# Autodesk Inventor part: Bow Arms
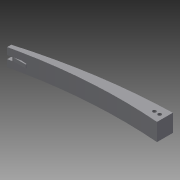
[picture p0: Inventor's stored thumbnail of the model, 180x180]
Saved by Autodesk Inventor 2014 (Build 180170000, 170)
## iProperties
Created: 2013-11
Part Number: Bow Arms
Material: Generic
Document SubType Name: Modeling
Designer: 603839
Density: 1 g/cm^3
Appearance: Default
Author: 603839
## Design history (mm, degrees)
sketch "Sketch1"
  geometry: L1 (-50.8, 15.875)-(50.8, 15.875); L2 (50.8, 15.875)-(50.8, -15.875); L3 (50.8, -15.875)-(-50.8, -15.875); L4 (-50.8, -15.875)-(-50.8, 15.875); L5 (-50.8, 15.875)-(50.8, -15.875); L6 (50.8, 15.875)-(-50.8, -15.875); 1 further point
  constraints: 12 end point, 2 midpoint, 2 parallel, 1 horizontal, 1 perpendicular
  dimensions: "d0" = 101.6 distance of L1.start L1.end; "d1" = 31.75 distance of L1.end L2.end
extrude "Extrusion1" new body sketch "Sketch1" distance "d2" = 19.05; taper "d3" = 0 deg
sketch "Sketch4"
  geometry: L1 (-50.8, -15.875)-(50.8, -15.875) reference; L2 (50.8, -15.875)-(50.8, 15.875) reference; L3 (50.8, 15.875)-(-50.8, 15.875) reference; L4 (-50.8, 15.875)-(-50.8, -15.875) reference; A1 r 402.075 centre (61.562, -386.056) between (50.8, 15.875) and (-50.8, 0); A2 r 337.58 centre (24.07, -332.178) between (50.8, 4.341) and (-50.8, -3.006); 1 further point
  constraints: 4 point on circle, 2 centre point, 2 point on line, 1 midpoint
extrude "Extrusion2" cut sketch "Sketch4" distance "d6" = 19.05; taper "d7" = 0 deg
sketch "Sketch5"
  geometry: L1 (-50.8, 0)-(-50.8, -3.006) reference; L2 (50.8, 4.341)-(50.8, 15.875) reference; A1 r 402.075 centre (61.562, -386.056) between (50.8, 15.875) and (-50.8, 0) reference; A2 r 337.58 centre (24.07, -332.178) between (50.8, 4.341) and (-50.8, -3.006) reference; 1 further point
extrude "Extrusion3" cut sketch "Sketch5" distance "d8" = 6.35; taper "d9" = 0 deg
hole "Hole1" diameter "d12" = 2.54; stored, may be unused: countersink angle "d16" = 82 deg, drill point angle "d18" = 118 deg; dims "d10" = 3.81, "d11" = 25.4, "d13" = 19.05, "d14" = 9.525, "d15" = 6.35, "d17" = 25.4
hole "Hole2" diameter "d21" = 2.54; stored, may be unused: countersink angle "d25" = 82 deg, drill point angle "d27" = 118 deg; dims "d19" = 7.62, "d20" = 25.4, "d22" = 19.05, "d23" = 9.525, "d24" = 6.35, "d26" = 25.4
sketch "Sketch6"
  geometry: L1 (3.006, 0)-(3.006, 5.08); L2 (3.006, 12.7)-(3.006, 7.62); L3 (3.006, 5.08)-(0, 5.08); L4 (0, 7.62)-(3.006, 7.62); L5 (3.006, 7.62)-(3.006, 5.08); L6 (0, 7.62)-(-3.164, 7.62); L7 (-3.164, 5.08)-(-3.164, 7.62); L8 (-3.164, 5.08)-(0, 5.08)
  constraints: 16 end point, 3 perpendicular, 1 collinear, 1 horizontal, 1 parallel
  dimensions: "d28" = 5.08 distance of L1.start L1.end; "d29" = 5.08 distance of L2.start L2.end
extrude "Extrusion4" cut sketch "Sketch6" distance "d30" = 3.175; taper "d31" = 0 deg
sketch "Sketch7"
  geometry: L1 (50.8, 15.875)-(50.8, 4.341) reference; L2 (-46.995, -2.163)-(-38.197, -2.163); L3 (-38.197, -2.163)-(-38.197, -1.503); L4 (-38.197, -1.503)-(-42.302, -1.188); A1 r 337.58 centre (24.07, -332.178) between (50.8, 4.341) and (-50.8, -3.006) reference; 1 further point
  constraints: 6 end point, 2 perpendicular, 2 point on circle
extrude "Extrusion5" join sketch "Sketch7" distance "d32" = 12.7; taper "d33" = 0 deg
sketch "Sketch8"
  geometry: L1 (-42.302, 1.188)-(-38.197, 1.503) reference; L2 (-38.197, 1.503)-(-38.197, 2.163) reference; L3 (-38.197, 2.163)-(-46.995, 2.163) reference; L4 (-46.995, 2.163)-(-38.197, 2.163); L5 (-38.197, 2.163)-(-38.197, 1.503); L6 (-38.197, 1.503)-(-42.302, 1.188); L7 (-42.302, 1.188)-(-46.995, 2.163); 1 further point
  constraints: 8 end point, 3 collinear
extrude "Extrusion6" cut sketch "Sketch8" distance "d34" = 5.08; taper "d35" = 0 deg
sketch "Sketch9"
  geometry: L1 (-46.995, -2.163)-(-38.197, -2.163) reference; L2 (-38.197, -2.163)-(-38.197, -1.503) reference; L3 (-38.197, -1.503)-(-42.302, -1.188) reference; L4 (-46.995, -2.163)-(-38.197, -2.163); L5 (-38.197, -2.163)-(-38.197, -1.503); L6 (-38.197, -1.503)-(-42.302, -1.188); L7 (-42.302, -1.188)-(-46.995, -2.163); 1 further point
  constraints: 8 end point, 3 collinear
extrude "Extrusion7" cut sketch "Sketch9" distance "d36" = 5.08; taper "d37" = 0 deg
body "Solid1"
